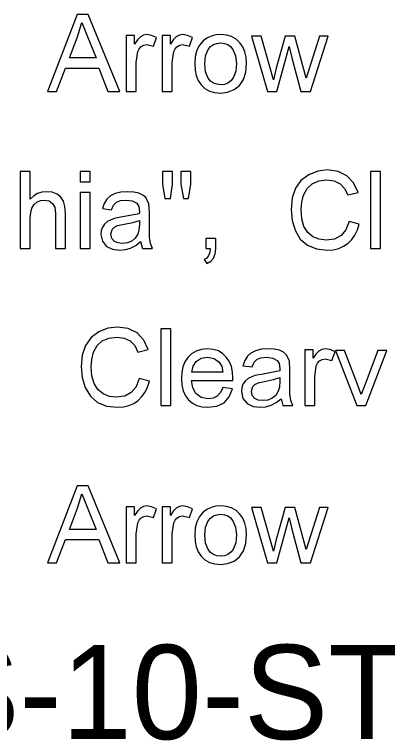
# Model space of a CAD drawing. Extents: x 1001568 to 1002149, y 1840825 to 1841423.
# Drawn here: x 1001897.508 to 1001899.088, y 1841265.244 to 1841268.324 of the extents above; entities that cross this region are included whole.
import ezdxf

# ---------------------------------------------------------------- set-up
doc = ezdxf.new("R2010")
doc.units = 0
doc.layers.add('40', color=7, linetype='Continuous')
doc.layers.add('SIGNS', color=7, linetype='Continuous')

msp = doc.modelspace()

# ---------------------------------------------------------------- linework, layer by layer
at = {"layer": 'SIGNS'}
for points in [[(1001897.6482, 1841267.9976), (1001897.6862, 1841267.9976), (1001897.7244, 1841268.0969), (1001897.8647, 1841268.0969), (1001897.9038, 1841267.9976), (1001897.9544, 1841267.9976), (1001897.8205, 1841268.3238), (1001897.7739, 1841268.3238), (1001897.6482, 1841267.9976)], [(1001897.7408, 1841268.1394), (1001897.7754, 1841268.2291), (1001897.7938, 1841268.2904), (1001897.818, 1841268.2258), (1001897.8535, 1841268.1394), (1001897.7408, 1841268.1394)], [(1001898.2716, 1841268.1146), (1001898.2732, 1841268.0882), (1001898.2783, 1841268.0648), (1001898.2868, 1841268.0439), (1001898.2987, 1841268.0261), (1001898.3147, 1841268.0104), (1001898.334, 1841267.9992), (1001898.3561, 1841267.9927), (1001898.3816, 1841267.9905), (1001898.411, 1841267.9942), (1001898.4381, 1841268.005), (1001898.4614, 1841268.0232), (1001898.478, 1841268.0481), (1001898.488, 1841268.0796), (1001898.4914, 1841268.1179), (1001898.4897, 1841268.1431), (1001898.4843, 1841268.1659), (1001898.4755, 1841268.1862), (1001898.4632, 1841268.204), (1001898.4468, 1841268.2191), (1001898.4278, 1841268.23), (1001898.406, 1841268.2365), (1001898.3816, 1841268.2387), (1001898.3604, 1841268.2371), (1001898.3412, 1841268.2321), (1001898.3235, 1841268.2238), (1001898.3078, 1841268.2123), (1001898.2918, 1841268.1942), (1001898.2806, 1841268.1719), (1001898.2738, 1841268.1453), (1001898.2716, 1841268.1146)], [(1001898.3141, 1841268.1147), (1001898.3178, 1841268.1484), (1001898.329, 1841268.1753), (1001898.3388, 1841268.1875), (1001898.3509, 1841268.1963), (1001898.3651, 1841268.2015), (1001898.3816, 1841268.2033), (1001898.3975, 1841268.2015), (1001898.4114, 1841268.1964), (1001898.4235, 1841268.1878), (1001898.4336, 1841268.1758), (1001898.445, 1841268.149), (1001898.4489, 1841268.1161), (1001898.4452, 1841268.0818), (1001898.4343, 1841268.0545), (1001898.4243, 1841268.0419), (1001898.4122, 1841268.0329), (1001898.3979, 1841268.0276), (1001898.3816, 1841268.026), (1001898.3651, 1841268.0277), (1001898.3509, 1841268.0331), (1001898.3388, 1841268.0417), (1001898.329, 1841268.0539), (1001898.3178, 1841268.0807), (1001898.3141, 1841268.1147)], [(1001898.0422, 1841267.3602), (1001898.0502, 1841267.3309), (1001898.0922, 1841267.3309), (1001898.0838, 1841267.3523), (1001898.0798, 1841267.3791), (1001898.0796, 1841267.4298), (1001898.0796, 1841267.4831), (1001898.0776, 1841267.5199), (1001898.065, 1841267.547), (1001898.0522, 1841267.558), (1001898.035, 1841267.5659), (1001898.0135, 1841267.5705), (1001897.9878, 1841267.5721), (1001897.9586, 1841267.5698), (1001897.9339, 1841267.5637), (1001897.9146, 1841267.5539), (1001897.8993, 1841267.5401), (1001897.888, 1841267.5222), (1001897.8808, 1841267.5003), (1001897.9195, 1841267.4949), (1001897.928, 1841267.515), (1001897.9402, 1841267.528), (1001897.957, 1841267.5345), (1001897.9806, 1841267.5366), (1001898.007, 1841267.5331), (1001898.0258, 1841267.5231), (1001898.0341, 1841267.5095), (1001898.037, 1841267.4887), (1001898.0368, 1841267.4784), (1001897.966, 1841267.4647), (1001897.9307, 1841267.4587), (1001897.9022, 1841267.4456), (1001897.8896, 1841267.4347), (1001897.8808, 1841267.422), (1001897.8754, 1841267.4074), (1001897.8739, 1841267.3911), (1001897.8801, 1841267.3615), (1001897.8982, 1841267.3398), (1001897.9233, 1841267.3278), (1001897.9549, 1841267.3239), (1001897.9778, 1841267.3262), (1001898.0001, 1841267.333), (1001898.0215, 1841267.3443), (1001898.0422, 1841267.3602)], [(1001898.037, 1841267.4498), (1001898.037, 1841267.4343), (1001898.0353, 1841267.4097), (1001898.0306, 1841267.3921), (1001898.0196, 1841267.3746), (1001898.0049, 1841267.3622), (1001897.9861, 1841267.3546), (1001897.9636, 1841267.3522), (1001897.9457, 1841267.3544), (1001897.9312, 1841267.3611), (1001897.92, 1841267.374), (1001897.9164, 1841267.3917), (1001897.922, 1841267.4116), (1001897.931, 1841267.4212), (1001897.9445, 1841267.4282), (1001897.9722, 1841267.4339), (1001898.0099, 1841267.4412), (1001898.037, 1841267.4498)], [(1001898.3909, 1841266.7406), (1001898.3803, 1841266.7195), (1001898.3665, 1841266.7046), (1001898.3492, 1841266.6956), (1001898.3287, 1841266.6926), (1001898.299, 1841266.6985), (1001898.2763, 1841266.7162), (1001898.263, 1841266.7403), (1001898.2575, 1841266.7706), (1001898.4332, 1841266.7706), (1001898.4334, 1841266.7814), (1001898.4318, 1841266.807), (1001898.4268, 1841266.8301), (1001898.4185, 1841266.8506), (1001898.4068, 1841266.8688), (1001898.3908, 1841266.8848), (1001898.3719, 1841266.8962), (1001898.3501, 1841266.9031), (1001898.3256, 1841266.9054), (1001898.3002, 1841266.9031), (1001898.278, 1841266.8961), (1001898.2586, 1841266.8846), (1001898.2422, 1841266.8685), (1001898.2302, 1841266.8501), (1001898.2217, 1841266.8292), (1001898.2166, 1841266.8054), (1001898.2149, 1841266.7793), (1001898.2168, 1841266.7517), (1001898.2224, 1841266.7276), (1001898.2319, 1841266.7066), (1001898.2453, 1841266.6891), (1001898.2618, 1841266.6751), (1001898.2811, 1841266.6651), (1001898.303, 1841266.6592), (1001898.3278, 1841266.6572), (1001898.3657, 1841266.6621), (1001898.3958, 1841266.6767), (1001898.4178, 1841266.7011), (1001898.4321, 1841266.7354), (1001898.3909, 1841266.7406)], [(1001898.6374, 1841266.6935), (1001898.6454, 1841266.6643), (1001898.6874, 1841266.6643), (1001898.679, 1841266.6856), (1001898.675, 1841266.7125), (1001898.6748, 1841266.7631), (1001898.6748, 1841266.8164), (1001898.6728, 1841266.8532), (1001898.6603, 1841266.8803), (1001898.6474, 1841266.8913), (1001898.6302, 1841266.8992), (1001898.6087, 1841266.9038), (1001898.583, 1841266.9054), (1001898.5538, 1841266.9032), (1001898.5291, 1841266.8971), (1001898.5098, 1841266.8872), (1001898.4945, 1841266.8735), (1001898.4832, 1841266.8555), (1001898.476, 1841266.8336), (1001898.5147, 1841266.8283), (1001898.5232, 1841266.8483), (1001898.5355, 1841266.8613), (1001898.5522, 1841266.8678), (1001898.5758, 1841266.8699), (1001898.6022, 1841266.8664), (1001898.621, 1841266.8564), (1001898.6293, 1841266.8428), (1001898.6322, 1841266.8221), (1001898.632, 1841266.8117), (1001898.5612, 1841266.798), (1001898.5259, 1841266.792), (1001898.4974, 1841266.7789), (1001898.4848, 1841266.768), (1001898.476, 1841266.7553), (1001898.4706, 1841266.7407), (1001898.4691, 1841266.7244), (1001898.4753, 1841266.6948), (1001898.4935, 1841266.6731), (1001898.5185, 1841266.6611), (1001898.5501, 1841266.6572), (1001898.5731, 1841266.6595), (1001898.5953, 1841266.6664), (1001898.6167, 1841266.6777), (1001898.6374, 1841266.6935)], [(1001898.2587, 1841266.8061), (1001898.2645, 1841266.8313), (1001898.2783, 1841266.8515), (1001898.2995, 1841266.8654), (1001898.3261, 1841266.8699), (1001898.3538, 1841266.8644), (1001898.3758, 1841266.8482), (1001898.3858, 1841266.8306), (1001898.391, 1841266.8061), (1001898.2587, 1841266.8061)], [(1001898.6322, 1841266.7832), (1001898.6322, 1841266.7676), (1001898.6305, 1841266.7431), (1001898.6258, 1841266.7254), (1001898.6148, 1841266.7079), (1001898.6001, 1841266.6955), (1001898.5814, 1841266.688), (1001898.5589, 1841266.6855), (1001898.5409, 1841266.6878), (1001898.5264, 1841266.6944), (1001898.5152, 1841266.7074), (1001898.5117, 1841266.725), (1001898.5172, 1841266.7449), (1001898.5262, 1841266.7546), (1001898.5397, 1841266.7616), (1001898.5674, 1841266.7672), (1001898.6052, 1841266.7745), (1001898.6322, 1841266.7832)], [(1001897.6482, 1841265.9976), (1001897.6862, 1841265.9976), (1001897.7244, 1841266.0969), (1001897.8647, 1841266.0969), (1001897.9038, 1841265.9976), (1001897.9544, 1841265.9976), (1001897.8205, 1841266.3238), (1001897.7739, 1841266.3238), (1001897.6482, 1841265.9976)], [(1001897.7408, 1841266.1394), (1001897.7754, 1841266.2291), (1001897.7938, 1841266.2904), (1001897.818, 1841266.2258), (1001897.8535, 1841266.1394), (1001897.7408, 1841266.1394)], [(1001898.2716, 1841266.1146), (1001898.2732, 1841266.0882), (1001898.2783, 1841266.0648), (1001898.2868, 1841266.0439), (1001898.2987, 1841266.0261), (1001898.3147, 1841266.0104), (1001898.334, 1841265.9992), (1001898.3561, 1841265.9927), (1001898.3816, 1841265.9905), (1001898.411, 1841265.9942), (1001898.4381, 1841266.005), (1001898.4614, 1841266.0232), (1001898.478, 1841266.0481), (1001898.488, 1841266.0796), (1001898.4914, 1841266.1179), (1001898.4897, 1841266.1431), (1001898.4843, 1841266.1659), (1001898.4755, 1841266.1862), (1001898.4632, 1841266.204), (1001898.4468, 1841266.2191), (1001898.4278, 1841266.23), (1001898.406, 1841266.2365), (1001898.3816, 1841266.2387), (1001898.3604, 1841266.2371), (1001898.3412, 1841266.2321), (1001898.3235, 1841266.2238), (1001898.3078, 1841266.2123), (1001898.2918, 1841266.1942), (1001898.2806, 1841266.1719), (1001898.2738, 1841266.1453), (1001898.2716, 1841266.1146)], [(1001898.3141, 1841266.1147), (1001898.3178, 1841266.1484), (1001898.329, 1841266.1754), (1001898.3388, 1841266.1875), (1001898.3509, 1841266.1963), (1001898.3651, 1841266.2015), (1001898.3816, 1841266.2033), (1001898.3975, 1841266.2015), (1001898.4114, 1841266.1964), (1001898.4235, 1841266.1878), (1001898.4336, 1841266.1758), (1001898.445, 1841266.149), (1001898.4489, 1841266.1161), (1001898.4452, 1841266.0818), (1001898.4343, 1841266.0545), (1001898.4243, 1841266.0419), (1001898.4122, 1841266.0329), (1001898.3979, 1841266.0276), (1001898.3816, 1841266.026), (1001898.3651, 1841266.0277), (1001898.3509, 1841266.0331), (1001898.3388, 1841266.0417), (1001898.329, 1841266.0539), (1001898.3178, 1841266.0807), (1001898.3141, 1841266.1147)]]:
    msp.add_lwpolyline(points, dxfattribs=at)
for points in [[(1001897.9814, 1841267.9976), (1001898.0239, 1841267.9976), (1001898.0239, 1841268.1203), (1001898.0305, 1841268.1666), (1001898.0358, 1841268.1782), (1001898.0437, 1841268.1871), (1001898.0554, 1841268.1939), (1001898.068, 1841268.1962), (1001898.0967, 1841268.1898), (1001898.1102, 1841268.2261), (1001898.089, 1841268.2355), (1001898.0686, 1841268.2387), (1001898.0544, 1841268.2362), (1001898.0412, 1841268.2287), (1001898.0285, 1841268.2161), (1001898.0169, 1841268.1987), (1001898.0169, 1841268.2346), (1001897.9814, 1841268.2346)], [(1001898.1336, 1841267.9976), (1001898.1761, 1841267.9976), (1001898.1761, 1841268.1203), (1001898.1827, 1841268.1666), (1001898.188, 1841268.1782), (1001898.1959, 1841268.1871), (1001898.2076, 1841268.1939), (1001898.2202, 1841268.1962), (1001898.2488, 1841268.1898), (1001898.2623, 1841268.2261), (1001898.2412, 1841268.2355), (1001898.2208, 1841268.2387), (1001898.2066, 1841268.2362), (1001898.1933, 1841268.2287), (1001898.1807, 1841268.2161), (1001898.169, 1841268.1987), (1001898.169, 1841268.2346), (1001898.1336, 1841268.2346)], [(1001898.5798, 1841267.9976), (1001898.6194, 1841267.9976), (1001898.6722, 1841268.1878), (1001898.6837, 1841268.1397), (1001898.721, 1841267.9976), (1001898.7627, 1841267.9976), (1001898.8367, 1841268.2316), (1001898.7996, 1841268.2316), (1001898.7432, 1841268.0532), (1001898.6962, 1841268.2316), (1001898.6549, 1841268.2316), (1001898.6172, 1841268.0958), (1001898.6049, 1841268.0469), (1001898.5532, 1841268.2316), (1001898.5116, 1841268.2316)], [(1001897.5324, 1841267.3309), (1001897.5749, 1841267.3309), (1001897.5749, 1841267.4592), (1001897.5765, 1841267.484), (1001897.5813, 1841267.5027), (1001897.5897, 1841267.5167), (1001897.6025, 1841267.5275), (1001897.6177, 1841267.5344), (1001897.6341, 1841267.5366), (1001897.6547, 1841267.5329), (1001897.6694, 1841267.5221), (1001897.6783, 1841267.5044), (1001897.6813, 1841267.4796), (1001897.6813, 1841267.3309), (1001897.7239, 1841267.3309), (1001897.7239, 1841267.4803), (1001897.7216, 1841267.5087), (1001897.715, 1841267.5317), (1001897.7039, 1841267.5493), (1001897.6886, 1841267.5617), (1001897.6677, 1841267.5695), (1001897.6441, 1841267.5721), (1001897.624, 1841267.57), (1001897.6058, 1841267.5641), (1001897.5894, 1841267.5542), (1001897.5749, 1841267.5407), (1001897.5749, 1841267.6572), (1001897.5324, 1841267.6572)], [(1001897.7866, 1841267.6146), (1001897.8291, 1841267.6146), (1001897.8291, 1841267.6572), (1001897.7866, 1841267.6572)], [(1001898.1456, 1841267.5437), (1001898.1684, 1841267.5437), (1001898.1777, 1841267.6046), (1001898.1777, 1841267.6572), (1001898.1351, 1841267.6572), (1001898.1351, 1841267.6046)], [(1001898.2234, 1841267.5437), (1001898.2457, 1841267.5437), (1001898.2557, 1841267.6046), (1001898.2557, 1841267.6572), (1001898.2132, 1841267.6572), (1001898.2132, 1841267.6046)], [(1001898.9253, 1841267.4456), (1001898.9124, 1841267.4108), (1001898.892, 1841267.3861), (1001898.8641, 1841267.3713), (1001898.8287, 1841267.3664), (1001898.7995, 1841267.3701), (1001898.7726, 1841267.3812), (1001898.7504, 1841267.3994), (1001898.7345, 1841267.4247), (1001898.7251, 1841267.457), (1001898.7222, 1841267.4966), (1001898.7249, 1841267.5274), (1001898.7325, 1841267.5572), (1001898.7473, 1841267.5855), (1001898.7688, 1841267.6058), (1001898.797, 1841267.6178), (1001898.832, 1841267.6217), (1001898.8623, 1841267.6176), (1001898.8872, 1841267.6058), (1001898.9065, 1841267.5859), (1001898.9204, 1841267.5583), (1001898.9634, 1841267.5684), (1001898.9448, 1841267.6093), (1001898.9163, 1841267.6395), (1001898.8789, 1841267.6581), (1001898.8342, 1841267.6642), (1001898.7926, 1841267.6593), (1001898.7547, 1841267.6443), (1001898.7218, 1841267.6195), (1001898.6984, 1841267.5866), (1001898.6843, 1841267.5456), (1001898.6797, 1841267.4965), (1001898.6839, 1841267.4505), (1001898.6969, 1841267.4083), (1001898.7187, 1841267.3713), (1001898.7488, 1841267.3449), (1001898.787, 1841267.3291), (1001898.8335, 1841267.3239), (1001898.8587, 1841267.3257), (1001898.8818, 1841267.3312), (1001898.9026, 1841267.3403), (1001898.9215, 1841267.3534), (1001898.9373, 1841267.3692), (1001898.9506, 1841267.388), (1001898.961, 1841267.4097), (1001898.969, 1841267.4345)], [(1001899.0169, 1841267.3309), (1001899.0594, 1841267.3309), (1001899.0594, 1841267.6572), (1001899.0169, 1841267.6572)], [(1001897.7866, 1841267.3309), (1001897.8291, 1841267.3309), (1001897.8291, 1841267.568), (1001897.7866, 1841267.568)], [(1001898.3187, 1841267.3309), (1001898.337, 1841267.3309), (1001898.335, 1841267.3142), (1001898.3301, 1841267.3008), (1001898.3222, 1841267.2907), (1001898.3116, 1841267.2841), (1001898.323, 1841267.2671), (1001898.3396, 1841267.277), (1001898.3516, 1841267.2906), (1001898.3588, 1841267.308), (1001898.3612, 1841267.3294), (1001898.3612, 1841267.3735), (1001898.3187, 1841267.3735)], [(1001898.0361, 1841266.7789), (1001898.0231, 1841266.7442), (1001898.0027, 1841266.7195), (1001897.9748, 1841266.7046), (1001897.9394, 1841266.6997), (1001897.9102, 1841266.7034), (1001897.8834, 1841266.7146), (1001897.8611, 1841266.7328), (1001897.8452, 1841266.758), (1001897.8358, 1841266.7904), (1001897.8329, 1841266.8299), (1001897.8356, 1841266.8607), (1001897.8432, 1841266.8906), (1001897.858, 1841266.9188), (1001897.8795, 1841266.9391), (1001897.9077, 1841266.9511), (1001897.9428, 1841266.9551), (1001897.973, 1841266.9509), (1001897.9979, 1841266.9391), (1001898.0172, 1841266.9192), (1001898.0311, 1841266.8917), (1001898.0741, 1841266.9018), (1001898.0555, 1841266.9426), (1001898.027, 1841266.9729), (1001897.9896, 1841266.9914), (1001897.9449, 1841266.9976), (1001897.9033, 1841266.9926), (1001897.8654, 1841266.9776), (1001897.8325, 1841266.9528), (1001897.8091, 1841266.9199), (1001897.7951, 1841266.8789), (1001897.7904, 1841266.8298), (1001897.7946, 1841266.7838), (1001897.8076, 1841266.7416), (1001897.8294, 1841266.7046), (1001897.8596, 1841266.6782), (1001897.8978, 1841266.6624), (1001897.9442, 1841266.6572), (1001897.9695, 1841266.659), (1001897.9925, 1841266.6645), (1001898.0134, 1841266.6737), (1001898.0322, 1841266.6867), (1001898.048, 1841266.7025), (1001898.0613, 1841266.7213), (1001898.0718, 1841266.7431), (1001898.0797, 1841266.7679)], [(1001898.1276, 1841266.6643), (1001898.1701, 1841266.6643), (1001898.1701, 1841266.9905), (1001898.1276, 1841266.9905)], [(1001898.7375, 1841266.6643), (1001898.78, 1841266.6643), (1001898.78, 1841266.7869), (1001898.7866, 1841266.8333), (1001898.7919, 1841266.8449), (1001898.7997, 1841266.8538), (1001898.8115, 1841266.8605), (1001898.8241, 1841266.8629), (1001898.8527, 1841266.8564), (1001898.8662, 1841266.8928), (1001898.8451, 1841266.9022), (1001898.8247, 1841266.9054), (1001898.8105, 1841266.9028), (1001898.7972, 1841266.8953), (1001898.7846, 1841266.8828), (1001898.7729, 1841266.8654), (1001898.7729, 1841266.9013), (1001898.7375, 1841266.9013)], [(1001898.9586, 1841266.6643), (1001898.996, 1841266.6643), (1001899.0858, 1841266.8983), (1001899.0478, 1841266.8983), (1001898.9933, 1841266.7561), (1001898.9769, 1841266.7116), (1001898.9601, 1841266.7588), (1001898.9063, 1841266.8983), (1001898.8684, 1841266.8983)], [(1001897.9814, 1841265.9976), (1001898.0239, 1841265.9976), (1001898.0239, 1841266.1203), (1001898.0305, 1841266.1666), (1001898.0358, 1841266.1782), (1001898.0437, 1841266.1871), (1001898.0554, 1841266.1939), (1001898.068, 1841266.1962), (1001898.0967, 1841266.1898), (1001898.1102, 1841266.2261), (1001898.089, 1841266.2355), (1001898.0686, 1841266.2387), (1001898.0544, 1841266.2362), (1001898.0412, 1841266.2287), (1001898.0285, 1841266.2161), (1001898.0169, 1841266.1987), (1001898.0169, 1841266.2346), (1001897.9814, 1841266.2346)], [(1001898.1336, 1841265.9976), (1001898.1761, 1841265.9976), (1001898.1761, 1841266.1203), (1001898.1827, 1841266.1666), (1001898.188, 1841266.1782), (1001898.1959, 1841266.1871), (1001898.2076, 1841266.1939), (1001898.2202, 1841266.1962), (1001898.2488, 1841266.1898), (1001898.2623, 1841266.2261), (1001898.2412, 1841266.2355), (1001898.2208, 1841266.2387), (1001898.2066, 1841266.2362), (1001898.1933, 1841266.2287), (1001898.1807, 1841266.2161), (1001898.169, 1841266.1987), (1001898.169, 1841266.2346), (1001898.1336, 1841266.2346)], [(1001898.5798, 1841265.9976), (1001898.6194, 1841265.9976), (1001898.6722, 1841266.1878), (1001898.6837, 1841266.1397), (1001898.721, 1841265.9976), (1001898.7627, 1841265.9976), (1001898.8367, 1841266.2316), (1001898.7996, 1841266.2316), (1001898.7432, 1841266.0532), (1001898.6962, 1841266.2316), (1001898.6549, 1841266.2316), (1001898.6172, 1841266.0958), (1001898.6049, 1841266.0469), (1001898.5532, 1841266.2316), (1001898.5116, 1841266.2316)]]:
    msp.add_lwpolyline(points, close=True, dxfattribs=at)

# ---------------------------------------------------------------- texts
at = {"layer": '40'}
msp.add_text('SS-BPS-10-STA265+50EB', height=0.4, rotation=0, dxfattribs=at).set_placement((1001895.5672, 1841265.2492))

doc.saveas('drawing.dxf')
